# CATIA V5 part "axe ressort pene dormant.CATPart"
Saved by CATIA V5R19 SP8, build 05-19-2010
Part number: axe ressort pene dormant
Revision: ANY
Definition: UNKNOWN
Nomenclature: axe ressort pene dormant
Source: Unknown
Bounding box of the stored display mesh (mm): x 0 to 16, y -3 to 3, z -3 to 3
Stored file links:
  D:\Documents\1_Travail\1 - ac-limoges.fr\ac-limoges.fr\Emmanuel Maynard - STI2D_Turgot\2 -2I2D\2_SEQUENCE_Serrure_Biométrique\5-Spé_ITEC\Serrure_Bio_Eleve\axe ressort pene dormant.CATPart
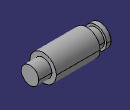
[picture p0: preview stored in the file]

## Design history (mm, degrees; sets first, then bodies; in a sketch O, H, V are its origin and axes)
Body1 "Révolution1" (main body)
  Solid1: solid without history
